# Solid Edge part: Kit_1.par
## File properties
Username: ahadarics
Dokumentum tartalom típus: 0
Author: ahadarics
Last saved by: psaghy
Revision: 78
Sűrűség: 0,000 kg/m^3
Pontosság: 0,990
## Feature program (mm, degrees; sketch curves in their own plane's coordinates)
base feature "unnamed BaseFeature 1"
thread "unnamed Thread 1"
chamfer "unnamed Chamfer 1"
sketch for "Furat_2" plane through (0, -41.625, 7) normal (0, 0, 1) x-axis (0, 1, 0)
  hole centre (0.625, 0) bore radius 5
hole "Furat_2" diameter 10 through
sketch for "Furat_3" plane through (0, -41.625, 7) normal (0, 0, 1) x-axis (0, 1, 0)
  hole centre (0.625, 0) bore radius 2.067
hole "Furat_3" nominal diameter 5 finite  ThreadDepth = 4.5 mm
chamfer "Letörés_2" setback 0.5
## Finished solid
Body 1: solid body, 50 faces, 55 edges, 8 vertices.
  Faces by surface: cylinder 16, plane 16, cone 11, torus 7
  Edges by curve: circle 47, line 6, intersection 2
Bounding box of the edges (mm; curved faces can reach further): 16.000 x 22.250 x 15.000, from (-8, -58, -8) to (8, -35.75, 7).
Cylindrical faces by radius (mm): R2.067 x2, R2.15 x2, R2.213 x1, R2.35 x1, R3.25 x1, R3.3 x1, R3.35 x1, R4.05 x1, R4.1 x1, R5.6 x2, R6 x2, R8 x1
Conical faces (half-angle, radius in mm at the cone's reference point): 5.7574 deg R3.25 x1, 12.9869 deg R2.0077 x1, 14.7799 deg R2.7245 x1, 15 deg R4.05 x1, 16.6443 deg R2.35 x1, 20.502 deg R2.513 x1, 45 deg R2.067 x1, 45 deg R3.4 x1, 45 deg R3.5 x1, 45 deg R6 x1, 60 deg R5.5 x1
Toroidal faces (ring radius, tube radius in mm): R2.2 r0.2 x1, R2.3 r0.3 x1, R2.9179 r0.2 x1, R3.1 r0.2 x1, R3.85 r0.2 x1, R4.09 r0.01 x2
Planar faces by outward normal: +y 5, +z 2, -y 9
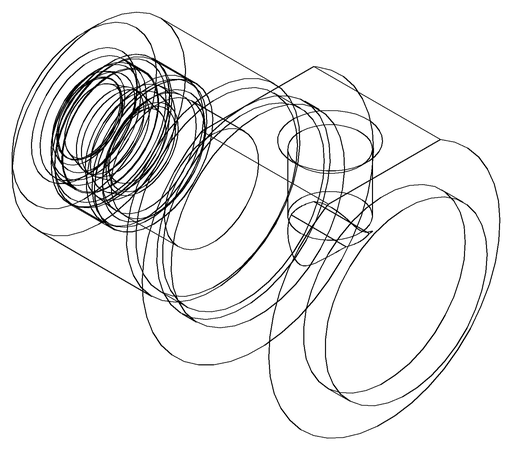
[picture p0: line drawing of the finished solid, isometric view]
